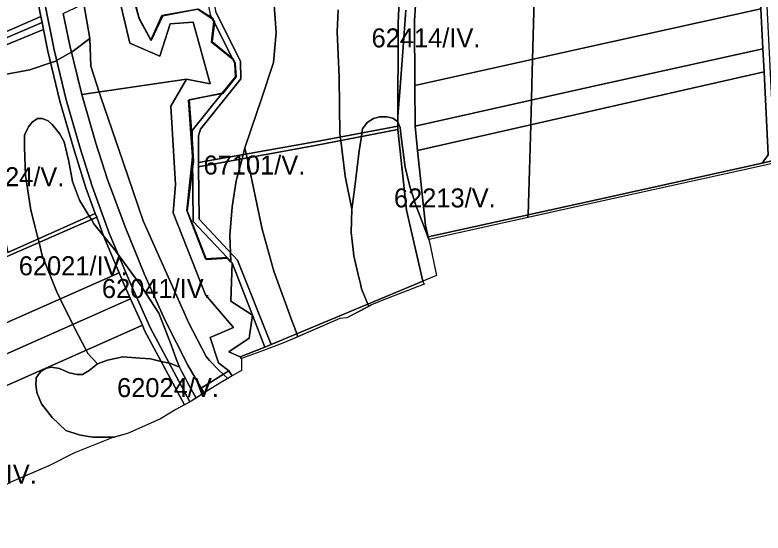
# Model space of a CAD drawing. Extents: x -522079 to -518792, y -1142400 to -1139961.
# Drawn here: x -520592 to -520002, y -1141917 to -1141508 of the extents above; entities that cross this region are included whole.
import ezdxf

# ---------------------------------------------------------------- set-up
doc = ezdxf.new("R2010")
doc.units = 0
for name, color, linetype in [('Hranice parcel', 7, 'Continuous'), ('Parcelní čísla', 7, 'Continuous'), ('Poz předměty', 7, 'Continuous'), ('Vnitřní kresba', 7, 'Continuous'), ('Značky bodu BP', 7, 'Continuous')]:
    doc.layers.add(name, color=color, linetype=linetype)

msp = doc.modelspace()

# ---------------------------------------------------------------- linework, layer by layer
at = {"layer": 'Hranice parcel'}
for points in [[(-519998.35, -1141618.37), (-520001.59, -1141552.99), (-520002.49, -1141534.74), (-520004.05, -1141503.1), (-520007.71, -1141429.14), (-520010.91, -1141364.55), (-520011.78, -1141349.43), (-520013.01, -1141327.96), (-520014.41, -1141303.65), (-520015.8, -1141279.3), (-520015.63, -1141269.2), (-520020.82, -1141261.97), (-520005.98, -1141266.96), (-520010.89, -1141271.2), (-520005.29, -1141383.92), (-519993.67, -1141617.6), (-519988.83, -1141621.62), (-520003.08, -1141624.98)], [(-520266.52, -1141683.24), (-520133.69, -1141653.91), (-520003.08, -1141624.98), (-519988.83, -1141621.62), (-519890.16, -1141599.67), (-519887.54, -1141601.15), (-519894.12, -1141602.61), (-519988.36, -1141623.57), (-520003.05, -1141627.05), (-520133.25, -1141655.87), (-520266.08, -1141685.14)]]:
    msp.add_lwpolyline(points, close=True, dxfattribs=at)
for points in [[(-520275.67, -1141487.93), (-520277.2, -1141512.43), (-520277.03, -1141563.71), (-520276.93, -1141594.74), (-520276.82, -1141595.78), (-520274.84, -1141614.95), (-520268.73, -1141674.23), (-520266.52, -1141683.24), (-520266.08, -1141685.14), (-520265.6, -1141687.35), (-520259.91, -1141713.53), (-520270.75, -1141718.04), (-520283.67, -1141662.22), (-520290.53, -1141598.43), (-520290.52, -1141595.71), (-520290.19, -1141514.57), (-520288.42, -1141473.23)], [(-520569.46, -1141496.36), (-520561.68, -1141535.49), (-520552.2, -1141574.91), (-520541.05, -1141613.27), (-520531.72, -1141643.02), (-520518.1, -1141680.34), (-520502.23, -1141718.09), (-520485.78, -1141754.61), (-520454.47, -1141813.35), (-520454.91, -1141813.57), (-520458.87, -1141815.72), (-520490.19, -1141756.96), (-520491.98, -1141752.99), (-520501.37, -1141732.13), (-520506.95, -1141719.75), (-520510.4, -1141711.55), (-520522.71, -1141682.28), (-520528.04, -1141667.68), (-520529.1, -1141664.77), (-520536.49, -1141644.52), (-520545.85, -1141614.67), (-520557.06, -1141576.08), (-520566.58, -1141536.47), (-520569.98, -1141519.36), (-520571.03, -1141514.08), (-520572, -1141509.22), (-520574.39, -1141497.17)], [(-520433.82, -1141506.13), (-520414.56, -1141544.64), (-520414.26, -1141558.37), (-520446.02, -1141598.19), (-520447.82, -1141603.5), (-520447.63, -1141624.46), (-520447.6, -1141627.85), (-520447.22, -1141669.1), (-520417.08, -1141701.53), (-520390.37, -1141768.15), (-520395.26, -1141770.17), (-520405.02, -1141744.98), (-520421.11, -1141703.69), (-520425.12, -1141699.44), (-520451.86, -1141671.07), (-520452.43, -1141620.06), (-520452.66, -1141599.19), (-520428.95, -1141569.87), (-520418.4, -1141556.83), (-520419, -1141546.21), (-520420.69, -1141542.88), (-520435.68, -1141513.27), (-520436.83, -1141511), (-520438.53, -1141507.64)]]:
    msp.add_lwpolyline(points, dxfattribs=at)
at = {"layer": 'Parcelní čísla'}
for points in [[(-520659.49, -1141438.15), (-520585.72, -1141406.64), (-520580.93, -1141457.51), (-520574.39, -1141497.17), (-520572, -1141509.22), (-520635.55, -1141536.73), (-520726.9, -1141576.27), (-520838.97, -1141624.77), (-520813.35, -1141504.9)], [(-520438.53, -1141507.64), (-520436.83, -1141511), (-520448.25, -1141503.52), (-520476.51, -1141508.33), (-520485.33, -1141527.78), (-520494.54, -1141511.04), (-520499.43, -1141490.33), (-520485.81, -1141474.99), (-520501.13, -1141439.65), (-520459.35, -1141430.33), (-520456.11, -1141417.28)], [(-520277.2, -1141512.43), (-520275.67, -1141487.93), (-520151.62, -1141461.03), (-520007.71, -1141429.14), (-520004.05, -1141503.1), (-520144.52, -1141534.29), (-520277.03, -1141563.71)], [(-520287.25, -1141456.97), (-520288.42, -1141473.23), (-520290.19, -1141514.57), (-520290.52, -1141595.71), (-520355.96, -1141608.22), (-520447.63, -1141624.46), (-520447.82, -1141603.5), (-520446.02, -1141598.19), (-520414.26, -1141558.37), (-520414.56, -1141544.64), (-520433.82, -1141506.13), (-520437.82, -1141485.59), (-520376.59, -1141474.28), (-520347.92, -1141468.69), (-520327.5, -1141464.71)], [(-520144.52, -1141534.29), (-520004.05, -1141503.1), (-520002.49, -1141534.74), (-520141.93, -1141565.64), (-520276.82, -1141595.78), (-520276.93, -1141594.74), (-520277.03, -1141563.71)], [(-520572, -1141509.22), (-520571.03, -1141514.08), (-520634.69, -1141540.99), (-520635.55, -1141536.73)], [(-520624.36, -1141541.82), (-520627.91, -1141548.79), (-520598.21, -1141695.54), (-520529.1, -1141664.77), (-520528.04, -1141667.68), (-520597.66, -1141698.25), (-520735.52, -1141758.79), (-520749.7, -1141765.02), (-520813.61, -1141793.09), (-520815.91, -1141783.74), (-520811.05, -1141786.45), (-520751.28, -1141760.21), (-520608.03, -1141697.31), (-520604.47, -1141690.49), (-520634.69, -1141540.99), (-520571.03, -1141514.08), (-520569.98, -1141519.36)], [(-520627.91, -1141548.79), (-520624.36, -1141541.82), (-520569.98, -1141519.36), (-520566.58, -1141536.47), (-520557.06, -1141576.08), (-520545.85, -1141614.67), (-520536.49, -1141644.52), (-520529.1, -1141664.77), (-520598.21, -1141695.54)], [(-520141.93, -1141565.64), (-520002.49, -1141534.74), (-520001.59, -1141552.99), (-520274.84, -1141614.95), (-520276.82, -1141595.78)], [(-520001.59, -1141552.99), (-519998.35, -1141618.37), (-520003.08, -1141624.98), (-520133.69, -1141653.91), (-520266.52, -1141683.24), (-520268.73, -1141674.23), (-520274.84, -1141614.95)], [(-520447.63, -1141624.46), (-520355.96, -1141608.22), (-520290.52, -1141595.71), (-520290.53, -1141598.43), (-520355.69, -1141611.08), (-520447.6, -1141627.85)], [(-520355.69, -1141611.08), (-520290.53, -1141598.43), (-520283.67, -1141662.22), (-520270.75, -1141718.04), (-520390.37, -1141768.15), (-520417.08, -1141701.53), (-520447.22, -1141669.1), (-520447.6, -1141627.85)], [(-520738.58, -1141765.16), (-520735.52, -1141758.79), (-520597.66, -1141698.25), (-520528.04, -1141667.68), (-520522.71, -1141682.28), (-520510.4, -1141711.55), (-520625.27, -1141762.24), (-520720.69, -1141804.35)], [(-520501.37, -1141732.13), (-520539.21, -1141748.91), (-520711.18, -1141825.18), (-520720.69, -1141804.35), (-520625.27, -1141762.24), (-520510.4, -1141711.55), (-520506.95, -1141719.75)], [(-520711.18, -1141825.18), (-520539.21, -1141748.91), (-520501.37, -1141732.13), (-520491.98, -1141752.99), (-520530.72, -1141770.15), (-520701.74, -1141845.88)], [(-520701.74, -1141845.88), (-520530.72, -1141770.15), (-520491.98, -1141752.99), (-520490.19, -1141756.96), (-520458.87, -1141815.72), (-520465.55, -1141819.35), (-520477.66, -1141826.82), (-520503.7, -1141838.29), (-520515.18, -1141841.56), (-520545.58, -1141853.73), (-520565.76, -1141863.93), (-520595.23, -1141876.48), (-520613.84, -1141887.11), (-520637.23, -1141899.54), (-520669.31, -1141916.94)]]:
    msp.add_lwpolyline(points, close=True, dxfattribs=at)
at = {"layer": 'Poz předměty'}
for points in [[(-520549.23, -1141532.17), (-520554.45, -1141506.79), (-520512.09, -1141486.67), (-520501.99, -1141530.25), (-520478.09, -1141540.57), (-520469.99, -1141514.94), (-520451.9, -1141513.8), (-520438.57, -1141562.32), (-520457.06, -1141558.71), (-520539.75, -1141570.9)], [(-520437.33, -1141529.38), (-520435.68, -1141513.27), (-520420.69, -1141542.88)], [(-520519.39, -1141637.97), (-520528.79, -1141609.27), (-520539.75, -1141570.9), (-520457.06, -1141558.71), (-520469.63, -1141579.9), (-520465.85, -1141641.84), (-520467.83, -1141664.2), (-520442.29, -1141729.04), (-520420.15, -1141754.6), (-520438.59, -1141762.62), (-520431.99, -1141782.5), (-520423.68, -1141788.92), (-520445.49, -1141802.61), (-520456.18, -1141784.44), (-520474.01, -1141749.11), (-520490.2, -1141712.81), (-520505.57, -1141675.34)], [(-520452.66, -1141599.19), (-520452.43, -1141620.06), (-520455.53, -1141575.25), (-520428.95, -1141569.87)], [(-520452.43, -1141620.06), (-520451.86, -1141671.07), (-520425.12, -1141699.44), (-520442.1, -1141700.42), (-520456.84, -1141662.39)], [(-520421.11, -1141703.69), (-520405.02, -1141744.98), (-520422.16, -1141733.79)], [(-520405.02, -1141744.98), (-520395.26, -1141770.17), (-520414.86, -1141777.92), (-520423.68, -1141774.01), (-520407.65, -1141762.99)], [(-520445.49, -1141802.61), (-520423.68, -1141788.92), (-520421.03, -1141792.82), (-520431, -1141798.52), (-520443.29, -1141806.35)]]:
    msp.add_lwpolyline(points, close=True, dxfattribs=at)
msp.add_lwpolyline([(-520554.45, -1141506.79), (-520549.23, -1141532.17), (-520539.75, -1141570.9), (-520528.79, -1141609.27), (-520519.39, -1141637.97), (-520505.57, -1141675.34), (-520490.2, -1141712.81), (-520474.01, -1141749.11), (-520456.18, -1141784.44), (-520445.49, -1141802.61), (-520443.29, -1141806.35), (-520453.46, -1141812.83), (-520454.47, -1141813.35), (-520485.78, -1141754.61), (-520502.23, -1141718.09), (-520518.1, -1141680.34), (-520531.72, -1141643.02), (-520541.05, -1141613.27), (-520552.2, -1141574.91), (-520561.68, -1141535.49), (-520569.46, -1141496.36)], dxfattribs=at)
at = {"layer": 'Vnitřní kresba'}
msp.add_lwpolyline([(-520499.43, -1141490.33), (-520494.54, -1141511.04), (-520485.33, -1141527.78), (-520476.51, -1141508.33), (-520448.25, -1141503.52), (-520436.83, -1141511), (-520435.68, -1141513.27), (-520437.33, -1141529.38), (-520420.69, -1141542.88), (-520419, -1141546.21), (-520418.4, -1141556.83), (-520428.95, -1141569.87), (-520455.53, -1141575.25), (-520452.43, -1141620.06), (-520456.84, -1141662.39), (-520442.1, -1141700.42), (-520425.12, -1141699.44), (-520421.11, -1141703.69), (-520422.16, -1141733.79), (-520405.02, -1141744.98), (-520407.65, -1141762.99), (-520423.68, -1141774.01), (-520414.86, -1141777.92), (-520413.8, -1141779.11), (-520413.91, -1141788.74), (-520421.03, -1141792.82), (-520423.68, -1141788.92), (-520431.99, -1141782.5), (-520438.59, -1141762.62), (-520420.15, -1141754.6), (-520442.29, -1141729.04), (-520467.83, -1141664.2), (-520465.85, -1141641.84), (-520469.63, -1141579.9), (-520457.06, -1141558.71), (-520438.57, -1141562.32), (-520451.9, -1141513.8), (-520469.99, -1141514.94), (-520478.09, -1141540.57), (-520501.99, -1141530.25), (-520512.09, -1141486.67)], dxfattribs=at)
msp.add_lwpolyline([(-520269.8, -1141720.57), (-520302.33, -1141733.12), (-520311.37, -1141736.89), (-520330.69, -1141747.06), (-520336.12, -1141747.68), (-520379.93, -1141766.64), (-520396.49, -1141772.96), (-520413.8, -1141779.11), (-520414.86, -1141777.92), (-520395.26, -1141770.17), (-520390.37, -1141768.15), (-520270.75, -1141718.04)], close=True, dxfattribs=at)
at = {"layer": 'Značky bodu BP'}
for points in [[(-520182.23, -1141467.67), (-520184.27, -1141543.11), (-520184.81, -1141562.76), (-520185.15, -1141575.29), (-520185.38, -1141583.8), (-520185.67, -1141594.73), (-520186.16, -1141612.72), (-520186.65, -1141630.59), (-520187.78, -1141665.85), (-520187.81, -1141666.87), (-520187.84, -1141667.9), (-520266.08, -1141685.14), (-520270.75, -1141672.69), (-520276.3, -1141658.15), (-520280.93, -1141643.31), (-520284.63, -1141628.15), (-520287.71, -1141606.19), (-520288.39, -1141599.37), (-520288.64, -1141596.91), (-520290.51, -1141592.62), (-520290.51, -1141592.44), (-520290.5, -1141592.15), (-520290.49, -1141587.84), (-520289.02, -1141568.32), (-520286.61, -1141536.74), (-520284.06, -1141504.23)], [(-519988.36, -1141623.57), (-520003.05, -1141627.05), (-520133.25, -1141655.87), (-520187.84, -1141667.9), (-520187.81, -1141666.87), (-520187.78, -1141665.85), (-520186.65, -1141630.59), (-520186.16, -1141612.72), (-520185.67, -1141594.73), (-520185.38, -1141583.8), (-520185.15, -1141575.29), (-520184.81, -1141562.76), (-520184.27, -1141543.11), (-520182.23, -1141467.67)], [(-520500.16, -1141491.1), (-520495.24, -1141508.09), (-520494.34, -1141511.19), (-520485.32, -1141527.76), (-520485.05, -1141528.25), (-520475.95, -1141508.61), (-520452.79, -1141504.29)], [(-520452.79, -1141504.29), (-520475.95, -1141508.61), (-520485.05, -1141528.25), (-520485.32, -1141527.76), (-520494.34, -1141511.19), (-520495.24, -1141508.09), (-520500.16, -1141491.1)], [(-520388.92, -1141488.89), (-520386.37, -1141521.76), (-520388.56, -1141545.5), (-520398.39, -1141575.08), (-520406.03, -1141597.36), (-520406.53, -1141598.9), (-520411.09, -1141612.94), (-520412.49, -1141618.23), (-520413.38, -1141621.6), (-520417.93, -1141638.86), (-520421.13, -1141659.42), (-520423.05, -1141681.7), (-520422.76, -1141688.95), (-520422.48, -1141695.72), (-520422.2, -1141702.53), (-520422.18, -1141703.01), (-520424.92, -1141700.09), (-520441.4, -1141701.07), (-520441.66, -1141700.39), (-520450.1, -1141678.98), (-520456.54, -1141662.67), (-520452.32, -1141629.43), (-520451.6, -1141623.72), (-520452.54, -1141610.09), (-520454.95, -1141575.13), (-520454.95, -1141575.07), (-520445.78, -1141573.27), (-520429.11, -1141570.07), (-520428.51, -1141569.95), (-520418.13, -1141556.81), (-520418.7, -1141546.41), (-520418.72, -1141545.96), (-520420.41, -1141542.62), (-520421.11, -1141542.05), (-520436.88, -1141529.11), (-520435.22, -1141514.18), (-520435.19, -1141513.9), (-520435.13, -1141513.44), (-520435.76, -1141512.19), (-520436.54, -1141510.66), (-520436.95, -1141510.39), (-520437.23, -1141510.21), (-520447.92, -1141503.38)], [(-520337.58, -1141503.86), (-520338.31, -1141521.4), (-520336.85, -1141557.19), (-520336.49, -1141579.74), (-520336.13, -1141602.11), (-520335.99, -1141603.26), (-520335.85, -1141604.37), (-520335.67, -1141605.9), (-520335.52, -1141607.16), (-520332.12, -1141635.35), (-520326.87, -1141661.24), (-520327.18, -1141679.81), (-520325.78, -1141693.16), (-520325.25, -1141698.2), (-520320.93, -1141716.28), (-520320.27, -1141719.01), (-520319.05, -1141724.12), (-520314.19, -1141736.24), (-520313.48, -1141738), (-520330.69, -1141747.06), (-520336.12, -1141747.68), (-520369.34, -1141762.06), (-520370.2, -1141759.7), (-520371.81, -1141755.28), (-520373.72, -1141750.04), (-520388.24, -1141710.2), (-520397.43, -1141677.2), (-520409.4, -1141620.88), (-520410.04, -1141617.88), (-520410.06, -1141617.8), (-520411.09, -1141612.94), (-520406.53, -1141598.9), (-520406.03, -1141597.36), (-520398.39, -1141575.08), (-520388.56, -1141545.5), (-520386.37, -1141521.76), (-520388.92, -1141488.89)], [(-520538.18, -1141499.21), (-520533.32, -1141526.62), (-520547.49, -1141537.2), (-520547.94, -1141537.45), (-520548.3, -1141537.66), (-520559.63, -1141544.02), (-520560.32, -1141544.41), (-520564.35, -1141545.75), (-520580.87, -1141551.24), (-520600.51, -1141555.1)], [(-520447.92, -1141503.38), (-520437.23, -1141510.21), (-520436.95, -1141510.39), (-520436.54, -1141510.66), (-520435.76, -1141512.19), (-520435.13, -1141513.44), (-520435.19, -1141513.9), (-520435.22, -1141514.18), (-520436.88, -1141529.11), (-520421.11, -1141542.05), (-520420.41, -1141542.62), (-520418.72, -1141545.96), (-520418.7, -1141546.41), (-520418.13, -1141556.81), (-520428.51, -1141569.95), (-520429.11, -1141570.07), (-520445.78, -1141573.27), (-520454.95, -1141575.07), (-520454.95, -1141575.13), (-520452.54, -1141610.09), (-520451.6, -1141623.72), (-520452.32, -1141629.43), (-520456.54, -1141662.67), (-520450.1, -1141678.98), (-520441.66, -1141700.39), (-520441.4, -1141701.07), (-520424.92, -1141700.09), (-520422.18, -1141703.01), (-520422.2, -1141702.53), (-520422.48, -1141695.72), (-520422.76, -1141688.95), (-520423.05, -1141681.7), (-520421.13, -1141659.42), (-520417.93, -1141638.86), (-520413.38, -1141621.6), (-520412.49, -1141618.23), (-520411.09, -1141612.94), (-520410.06, -1141617.8), (-520410.04, -1141617.88), (-520409.4, -1141620.88), (-520397.43, -1141677.2), (-520388.24, -1141710.2), (-520373.72, -1141750.04), (-520371.81, -1141755.28), (-520370.2, -1141759.7), (-520369.34, -1141762.06), (-520379.93, -1141766.64), (-520396.49, -1141772.96), (-520413.8, -1141779.11), (-520413.91, -1141788.74), (-520421.03, -1141792.82), (-520424.57, -1141794.84), (-520428.07, -1141791.67), (-520432.21, -1141787.93), (-520438.98, -1141780.65), (-520441.75, -1141777.67), (-520455.58, -1141750.83), (-520457.31, -1141746.95), (-520491.41, -1141670.41), (-520507.21, -1141624.31), (-520524.82, -1141572.93), (-520525.36, -1141571.25), (-520526.12, -1141568.89), (-520532.71, -1141548.56), (-520533.32, -1141526.62), (-520538.18, -1141499.21)], [(-520284.06, -1141504.23), (-520286.61, -1141536.74), (-520289.02, -1141568.32), (-520290.49, -1141587.84), (-520290.5, -1141592.15), (-520290.68, -1141592.04), (-520290.8, -1141591.96), (-520291.47, -1141591.51), (-520292.65, -1141590.71), (-520294.5, -1141589.48), (-520299.12, -1141588.55), (-520304.67, -1141588.55), (-520309.61, -1141589.79), (-520314.54, -1141592.88), (-520318.24, -1141597.83), (-520318.76, -1141601.11), (-520319.23, -1141604), (-520321.02, -1141615.16), (-520324.72, -1141645.78), (-520325.52, -1141651.55), (-520326.87, -1141661.24), (-520332.12, -1141635.35), (-520335.52, -1141607.16), (-520335.67, -1141605.9), (-520335.85, -1141604.37), (-520335.99, -1141603.26), (-520336.13, -1141602.11), (-520336.49, -1141579.74), (-520336.85, -1141557.19), (-520338.31, -1141521.4), (-520337.58, -1141503.86)], [(-520600.51, -1141555.1), (-520580.87, -1141551.24), (-520564.35, -1141545.75), (-520560.32, -1141544.41), (-520559.63, -1141544.02), (-520548.3, -1141537.66), (-520547.94, -1141537.45), (-520547.49, -1141537.2), (-520533.32, -1141526.62), (-520532.71, -1141548.56), (-520526.12, -1141568.89), (-520525.36, -1141571.25), (-520524.82, -1141572.93), (-520507.21, -1141624.31), (-520491.41, -1141670.41), (-520457.31, -1141746.95), (-520455.58, -1141750.83), (-520441.75, -1141777.67), (-520438.98, -1141780.65), (-520432.21, -1141787.93), (-520428.07, -1141791.67), (-520424.57, -1141794.84), (-520431, -1141798.52), (-520443.29, -1141806.35), (-520449.65, -1141810.4), (-520456.02, -1141798.53), (-520457.63, -1141795.53), (-520460.89, -1141789.6), (-520462.79, -1141786.14), (-520465.25, -1141779.44), (-520469.34, -1141768.28), (-520475.29, -1141752.85), (-520478.95, -1141743.38), (-520492.77, -1141722.23), (-520503.19, -1141707.88), (-520511.09, -1141697.01), (-520512.91, -1141694.51), (-520522.71, -1141682.28), (-520530.24, -1141672.89), (-520532.25, -1141669.53), (-520533.84, -1141666.88), (-520541.48, -1141654.1), (-520547.1, -1141639.53), (-520549.91, -1141623.55), (-520553.66, -1141608.04), (-520557.41, -1141601.47), (-520563.03, -1141594.42), (-520566.31, -1141591.6), (-520570.99, -1141589.72), (-520574.74, -1141589.72), (-520578.96, -1141592.54), (-520581.77, -1141596.3), (-520582.5, -1141597.77), (-520585.04, -1141602.88), (-520585.04, -1141612.75), (-520584.11, -1141634.83), (-520579.89, -1141662.08), (-520577.05, -1141673.47), (-520574.22, -1141684.86), (-520573.52, -1141687.65), (-520570.99, -1141697.79), (-520559.75, -1141725.99), (-520556.79, -1141732.02), (-520546.85, -1141752.29), (-520545.23, -1141755.59), (-520536.33, -1141772.63), (-520534.92, -1141775.33), (-520527.43, -1141783.32), (-520533.99, -1141788.72), (-520539.14, -1141791.77), (-520543.36, -1141791.77), (-520549.68, -1141790.36), (-520557.41, -1141787.08), (-520563.97, -1141785.9), (-520567.48, -1141786.84), (-520572.16, -1141789.43), (-520573.92, -1141791.89), (-520575.68, -1141794.36), (-520575.86, -1141796.39), (-520576.14, -1141799.53), (-520575.21, -1141806.11), (-520571.69, -1141815.03), (-520563.03, -1141825.61), (-520552.26, -1141835.94), (-520541.95, -1141839.47), (-520536.09, -1141840.47), (-520530.94, -1141841.35), (-520521.57, -1141841.35), (-520513.92, -1141841.2), (-520515.18, -1141841.56), (-520545.58, -1141853.73), (-520565.76, -1141863.93), (-520575.63, -1141868.13), (-520595.23, -1141876.48)]]:
    msp.add_lwpolyline(points, dxfattribs=at)
for points in [[(-520469.34, -1141768.28), (-520465.25, -1141779.44), (-520462.79, -1141786.14), (-520469.58, -1141783.08), (-520470.74, -1141782.83), (-520477.16, -1141781.41), (-520485.51, -1141779.56), (-520493.76, -1141778.93), (-520507.29, -1141777.91), (-520519.47, -1141780.5), (-520527.43, -1141783.32), (-520534.92, -1141775.33), (-520536.33, -1141772.63), (-520545.23, -1141755.59), (-520546.85, -1141752.29), (-520556.79, -1141732.02), (-520559.75, -1141725.99), (-520570.99, -1141697.79), (-520573.52, -1141687.65), (-520574.22, -1141684.86), (-520577.05, -1141673.47), (-520579.89, -1141662.08), (-520584.11, -1141634.83), (-520585.04, -1141612.75), (-520585.04, -1141602.88), (-520582.5, -1141597.77), (-520581.77, -1141596.3), (-520578.96, -1141592.54), (-520574.74, -1141589.72), (-520570.99, -1141589.72), (-520566.31, -1141591.6), (-520563.03, -1141594.42), (-520557.41, -1141601.47), (-520553.66, -1141608.04), (-520549.91, -1141623.55), (-520547.1, -1141639.53), (-520541.48, -1141654.1), (-520533.84, -1141666.88), (-520532.25, -1141669.53), (-520530.24, -1141672.89), (-520522.71, -1141682.28), (-520512.91, -1141694.51), (-520511.09, -1141697.01), (-520503.19, -1141707.88), (-520492.77, -1141722.23), (-520478.95, -1141743.38), (-520475.29, -1141752.85)], [(-520265.77, -1141686.57), (-520265.6, -1141687.35), (-520259.91, -1141713.53), (-520270.75, -1141718.04), (-520269.8, -1141720.57), (-520302.33, -1141733.12), (-520311.37, -1141736.89), (-520313.48, -1141738), (-520314.19, -1141736.24), (-520319.05, -1141724.12), (-520320.27, -1141719.01), (-520320.93, -1141716.28), (-520325.25, -1141698.2), (-520325.78, -1141693.16), (-520327.18, -1141679.81), (-520326.87, -1141661.24), (-520325.52, -1141651.55), (-520324.72, -1141645.78), (-520321.02, -1141615.16), (-520319.23, -1141604), (-520318.76, -1141601.11), (-520318.24, -1141597.83), (-520314.54, -1141592.88), (-520309.61, -1141589.79), (-520304.67, -1141588.55), (-520299.12, -1141588.55), (-520294.5, -1141589.48), (-520292.65, -1141590.71), (-520291.47, -1141591.51), (-520290.8, -1141591.96), (-520290.68, -1141592.04), (-520290.5, -1141592.15), (-520290.51, -1141592.44), (-520290.51, -1141592.62), (-520288.64, -1141596.91), (-520288.39, -1141599.37), (-520287.71, -1141606.19), (-520284.63, -1141628.15), (-520280.93, -1141643.31), (-520276.3, -1141658.15), (-520270.75, -1141672.69), (-520266.08, -1141685.14)], [(-520477.66, -1141826.82), (-520480.51, -1141828.07), (-520503.7, -1141838.29), (-520513.92, -1141841.2), (-520521.57, -1141841.35), (-520530.94, -1141841.35), (-520536.09, -1141840.47), (-520541.95, -1141839.47), (-520552.26, -1141835.94), (-520563.03, -1141825.61), (-520571.69, -1141815.03), (-520575.21, -1141806.11), (-520576.14, -1141799.53), (-520575.86, -1141796.39), (-520575.68, -1141794.36), (-520573.92, -1141791.89), (-520572.16, -1141789.43), (-520567.48, -1141786.84), (-520563.97, -1141785.9), (-520557.41, -1141787.08), (-520549.68, -1141790.36), (-520543.36, -1141791.77), (-520539.14, -1141791.77), (-520533.99, -1141788.72), (-520527.43, -1141783.32), (-520519.47, -1141780.5), (-520507.29, -1141777.91), (-520493.76, -1141778.93), (-520485.51, -1141779.56), (-520477.16, -1141781.41), (-520470.74, -1141782.83), (-520469.58, -1141783.08), (-520462.79, -1141786.14), (-520460.89, -1141789.6), (-520457.63, -1141795.53), (-520456.02, -1141798.53), (-520449.65, -1141810.4), (-520453.46, -1141812.83), (-520454.47, -1141813.35), (-520454.91, -1141813.57), (-520458.87, -1141815.72), (-520465.55, -1141819.35)]]:
    msp.add_lwpolyline(points, close=True, dxfattribs=at)

# ---------------------------------------------------------------- texts
for s, rotation, p in [('62414/IV.', 360, (-520311.18, -1141533.62)), ('67101/V.', 0, (-520443.76, -1141633.97)), ('62024/V.', 0, (-520633.79, -1141643.17)), ('62213/V.', 0, (-520293.55, -1141659.92)), ('62021/IV.', 360, (-520589.49, -1141713.49)), ('62024/V.', 360, (-520511.94, -1141809.63)), ('62041/IV.', 360, (-520661.11, -1141877.91))]:
    msp.add_text(s, height=15, rotation=rotation, dxfattribs=at).set_placement(p)
msp.add_text('62041/IV.', height=15, dxfattribs=at).set_placement((-520523.91, -1141731.43))

doc.saveas('drawing.dxf')
